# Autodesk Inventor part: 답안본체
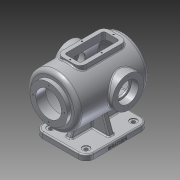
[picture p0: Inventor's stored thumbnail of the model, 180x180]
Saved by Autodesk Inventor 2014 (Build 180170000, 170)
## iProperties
Created: 2021-11
Part Number: 답안본체
Material: 알루미늄 6061
Document SubType Name: Modeling
Designer: kb
Density: 2.71 g/cm^3
Appearance: 알루미늄 - 평지
Mass: 3553.3 g
Surface Area: 2413.01 cm^2
Volume: 1311.18 cm^3
Author: kb
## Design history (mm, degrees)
sketch "스케치1"
  geometry: L1 (0, 0)-(220, 0); L2 (185.993, 65)-(10, 65); L3 (10, 65)-(10, 47.5); L4 (10, 47.5)-(0, 47.5); L5 (0, 47.5)-(0, 32.5); L6 (0, 32.5)-(25, 32.5); L7 (25, 32.5)-(25, 52); L8 (28, 55)-(179.75, 55); A1 r 100 centre (110, 0) between (210, 0) and (185.993, 65); A2 r 90 centre (110, 0) between (200, 0) and (182.155, 53.793); A3 r 3 centre (28, 52) between (28, 55) and (25, 52); A4 r 3 centre (179.75, 52) between (182.155, 53.793) and (179.75, 55); 2 further points
  constraints: 16 end point, 9 point on circle, 5 point on line, 4 centre point, 4 perpendicular, 4 tangent, 2 parallel, 1 coincident, 1 horizontal, 1 midpoint, 1 vertical alignment
  dimensions: "d0" = 130 diameter of L2 L1; "d2" = 95 diameter of L4 L1; "d3" = 110 diameter of L8 L1; "d4" = 65 diameter of L6 L1; "d6" = 10 distance of L3.end L4.end; "d9" = 25 distance between parallel lines of L7 L5; "d13" = 100 radius of A1; "d14" = 10 radial gap between concentric circles of A1 A2; "d15" = 210 distance from line of A1.start L5; "d17" = 3 radius of A3; "d18" = 3 radius of A4
revolve "회전1" sketch "스케치1" stored, may be unused: angle "d10" = 90 deg
fillet "모깎기1" dims "d16" = 10
node "작업 평면1"
sketch "스케치2"
  geometry: L1 (47.5, 0)-(-47.5, 0) reference; L2 (-45, 190)-(45, 190); L3 (65, 170)-(65, 50); L4 (45, 30)-(-45, 30); L5 (-65, 50)-(-65, 170); A1 r 100 centre (0, 110) between (61.111, 189.154) and (-61.111, 189.154) reference; A2 r 20 centre (-45, 170) between (-45, 190) and (-65, 170); A3 r 20 centre (-45, 50) between (-65, 50) and (-45, 30); A4 r 20 centre (45, 50) between (45, 30) and (65, 50); A5 r 20 centre (45, 170) between (65, 170) and (45, 190); 9 further points
  constraints: 8 end point, 8 point on circle, 8 tangent, 6 point on line, 4 centre point, 4 coincident, 3 equal radius, 2 parallel, 1 horizontal, 1 midpoint, 1 perpendicular, 1 vertical alignment
  dimensions: "d20" = 130 distance of point (-65, 190) point (65, 190); "d21" = 160 distance of point (65, 190) point (65, 30); "d22" = 30 distance between parallel lines of L4 L1; "d23" = 20 radius of A2
extrude "돌출1" join sketch "스케치2" distance "d24" = 14; taper "d25" = 0 deg
sketch "스케치3"
  geometry: A1 r 20 centre (-45, 50) between (-65, 50) and (-45, 30) reference; A2 r 20 centre (45, 50) between (45, 30) and (65, 50) reference; A3 r 20 centre (45, 170) between (65, 170) and (45, 190) reference; A4 r 20 centre (-45, 170) between (-45, 190) and (-65, 170) reference; 5 further points
  constraints: 4 coincident
hole "구멍1" sketch "스케치3" at (-45, 50), (45, 170), (45, 50), (-45, 170) diameter "d26" = 9; stored, may be unused: countersink angle "d30" = 90 deg, drill point angle "d32" = 118 deg; dims "d27" = 6, "d28" = 18, "d29" = 2, "d31" = 12
node "작업 평면2"
sketch "스케치4"
  geometry: L1 (45, 114)-(45, -1.6); L2 (90, 14)-(0, 14) reference; L3 (11.261, 58.442)-(-5, 13.765); L4 (78.739, 58.442)-(95, 13.765); L5 (110, 14)-(90, 14) reference; L6 (-9, 14)-(9, 14) reference; L7 (-5, 13.765)-(95, 13.765); L8 (94.5, 12)-(85.5, 12) reference; A1 r 65 centre (45, 114) between (11.261, 58.442) and (11.261, 58.442) reference; A2 r 65 centre (45, 114) between (11.261, 58.442) and (78.739, 58.442); 2 further points
  constraints: 8 end point, 4 point on circle, 2 symmetric about line, 1 centre point, 1 concentric, 1 midpoint, 1 parallel, 1 perpendicular, 1 vertical alignment, 1 other
  dimensions: "d40" = 100 distance of L4.end L3.end; "d41" = 110 deg angle of L5 L4; "d42" = 110 deg angle of L6 L3 (derived); "d43" = 14.17568 distance from line of L5.start L4; "d44" = 15.60038 distance from line of L1.end L2
sketch "스케치5"
  geometry: 1 further point
extrude "돌출3" join sketch "스케치4" stored distance "d45" = 14; taper "d46" = 0 deg
sketch "스케치6"
  geometry: L1 (20, -65)-(181.239, -65) reference; L2 (170, -100)-(50, -100) reference; L3 (62.739, -65)-(50, -100); L4 (41, -100)-(59, -100) reference; L5 (190, -100)-(170, -100) reference; L6 (157.261, -65)-(170, -100); L7 (103, -100)-(117, -100) reference; L8 (103, -55.558)-(103, -100) reference; L9 (117, -55.558)-(103, -55.558) reference; L10 (117, -100)-(117, -55.558) reference; L11 (117, -100)-(117, -55.558) reference; L12 (110, -55.558)-(110, -100); 1 further point
  constraints: 6 end point, 3 midpoint, 2 point on line, 1 other
  dimensions: "d117" = 120 distance of L2.start L2.end (derived); "d118" = 110 deg angle of L5 L6
  node "투영된 루프1"
feature "리브1" dims "d50" = 1, "d51" = 14, "d52" = 0, "d53" = 0, "d54" = 1, "d55" = 1
feature "리브2" dims "d56" = 1, "d57" = 14, "d58" = 0, "d59" = 0, "d60" = 1, "d61" = 1
node "작업 평면3"
sketch "스케치7"
  geometry: L1 (0, -47.5)-(0, 47.5) reference; C1 r 40 at (127, 0); 2 further points
  constraints: 1 centre point, 1 horizontal alignment, 1 midpoint
  dimensions: "d63" = 127 distance from line of C1.centre L1; "d64" = 80 diameter of C1
extrude "돌출4" join sketch "스케치7" stored distance "d65" = 14; taper "d66" = 0 deg
hole "구멍2" diameter "d69" = 42; stored, may be unused: countersink angle "d73" = 90 deg, drill point angle "d75" = 118 deg; dims "d67" = 10, "d68" = 10, "d70" = 6, "d71" = 52, "d72" = 18, "d74" = 12
fillet "모깎기2" dims "d76" = 0.3
node "작업 평면4"
sketch "스케치8"
  geometry: L1 (-15, 170)-(15, 170); L2 (30, 155)-(30, 65); L3 (15, 50)-(-15, 50); L4 (-30, 65)-(-30, 155); L5 (47.5, 0)-(-47.5, 0) reference; A1 r 15 centre (-15, 155) between (-15, 170) and (-30, 155); A2 r 15 centre (-15, 65) between (-30, 65) and (-15, 50); A3 r 15 centre (15, 65) between (15, 50) and (30, 65); A4 r 15 centre (15, 155) between (30, 155) and (15, 170); 5 further points
  constraints: 8 end point, 8 point on circle, 8 tangent, 6 point on line, 4 centre point, 3 equal radius, 2 parallel, 1 horizontal, 1 midpoint, 1 perpendicular, 1 vertical alignment
  dimensions: "d78" = 120 distance of point (30, 170) point (30, 50); "d79" = 60 distance of point (-30, 170) point (30, 170); "d80" = 50 distance between parallel lines of L3 L5; "d81" = 15 radius of A1
extrude "돌출5" join sketch "스케치8" stored distance "d82" = 14; taper "d83" = 0 deg
sketch "스케치9"
  geometry: L1 (-30, 155)-(-30, 65) reference; L2 (-15, 50)-(15, 50) reference; L3 (30, 65)-(30, 155) reference; L4 (15, 170)-(-15, 170) reference; L5 (20, 155)-(20, 65); L6 (15, 60)-(-15, 60); L7 (-20, 65)-(-20, 155); L8 (-15, 160)-(15, 160); A1 r 15 centre (-15, 65) between (-30, 65) and (-15, 50) reference; A2 r 15 centre (15, 65) between (15, 50) and (30, 65) reference; A3 r 15 centre (15, 155) between (30, 155) and (15, 170) reference; A4 r 15 centre (-15, 155) between (-15, 170) and (-30, 155) reference; A5 r 5 centre (15, 155) between (20, 155) and (15, 160); A6 r 5 centre (15, 65) between (15, 60) and (20, 65); A7 r 5 centre (-15, 65) between (-20, 65) and (-15, 60); A8 r 5 centre (-15, 155) between (-15, 160) and (-20, 155); 1 further point
  constraints: 8 end point, 8 point on circle, 4 centre point, 7 other
  dimensions: "d84" = 10 distance between parallel lines of L3 L5
extrude "돌출6" cut sketch "스케치9" stored distance "d85" = 14; taper "d86" = 0 deg
sketch "스케치10"
  geometry: L1 (-30, 155)-(-30, 65) reference; L2 (-15, 50)-(15, 50) reference; L3 (30, 65)-(30, 155) reference; L4 (15, 170)-(-15, 170) reference; L5 (25, 155)-(25, 65); L6 (15, 55)-(-15, 55); L7 (-25, 65)-(-25, 155); L8 (-15, 165)-(15, 165); L9 (-25, 110)-(25, 110); L10 (0, 165)-(0, 55); A1 r 15 centre (-15, 65) between (-30, 65) and (-15, 50) reference; A2 r 15 centre (15, 65) between (15, 50) and (30, 65) reference; A3 r 15 centre (15, 155) between (30, 155) and (15, 170) reference; A4 r 15 centre (-15, 155) between (-15, 170) and (-30, 155) reference; A5 r 10 centre (15, 65) between (15, 55) and (25, 65); A6 r 10 centre (-15, 65) between (-25, 65) and (-15, 55); A7 r 10 centre (-15, 155) between (-15, 165) and (-25, 155); A8 r 10 centre (15, 155) between (25, 155) and (15, 165); 9 further points; 1 other entity
  constraints: 12 end point, 8 point on circle, 5 coincident, 4 centre point, 4 midpoint, 8 other
  dimensions: "d87" = 5 distance between parallel lines of L3 L5
hole "구멍3" sketch "스케치10" at (-25, 110), (0, 55), (25, 110), (0, 165) diameter "d88" = 3.242; stored, may be unused: countersink angle "d92" = 90 deg, drill point angle "d94" = 118 deg; dims "d89" = 9, "d90" = 52, "d91" = 18, "d93" = 11
sketch "스케치11"
  geometry: C1 r 26 at (0, 0) reference; C2 r 40 at (0, 0) reference; A1 r 32.5 centre (0, 0) between (0, 32.5) and (-32.5, 0); 3 further points
  constraints: 4 point on circle, 2 horizontal alignment, 2 vertical alignment, 1 centre point, 1 coincident
  dimensions: "d95" = 65 diameter of A1
hole "구멍4" sketch "스케치11" at (-32.5, 0), (0, -32.5), (32.5, 0), (0, 32.5) diameter "d96" = 3.242; stored, may be unused: countersink angle "d100" = 90 deg, drill point angle "d102" = 118 deg; dims "d97" = 11, "d98" = 52, "d99" = 18, "d101" = 13
sketch "스케치12"
  geometry: C1 r 32.5 at (0, 0) reference; C2 r 47.5 at (0, 0) reference; A1 r 40 centre (0, 0) between (0, 40) and (0, -40); 2 further points
  constraints: 4 point on circle, 2 horizontal alignment, 2 vertical alignment, 1 centre point, 1 coincident
  dimensions: "d103" = 80 diameter of A1
hole "구멍5" sketch "스케치12" at (0, 40), (-40, 0), (0, -40), (40, 0) diameter "d104" = 3.242; stored, may be unused: countersink angle "d108" = 90 deg, drill point angle "d110" = 118 deg; dims "d105" = 11, "d106" = 52, "d107" = 18, "d109" = 13
fillet "모깎기3" dims "d111" = 3
fillet "모깎기4" dims "d112" = 3
node "작업 평면5"
sketch "스케치13"
  geometry: L1 (0, 0)-(0, 120) reference; 3 further points
  constraints: 1 horizontal alignment, 1 midpoint, 1 other
  dimensions: "d114" = 5 distance from line of L1 point (-5, 60)
feature "엠보싱1" sketch "스케치13" dims "d0" = 130, "d2" = 95, "d3" = 110, "d4" = 65, "d6" = 10, "d9" = 25, "d13" = 100, "d14" = 10, "d15" = 210, "d17" = 3, "d18" = 3, "d115" = 0.5, "d116" = 0
node "솔리드1"
mirror "대칭1"
mirror "대칭2"
other parameters: "d19" = -114, "d62" = 75, "d113" = 48.25
